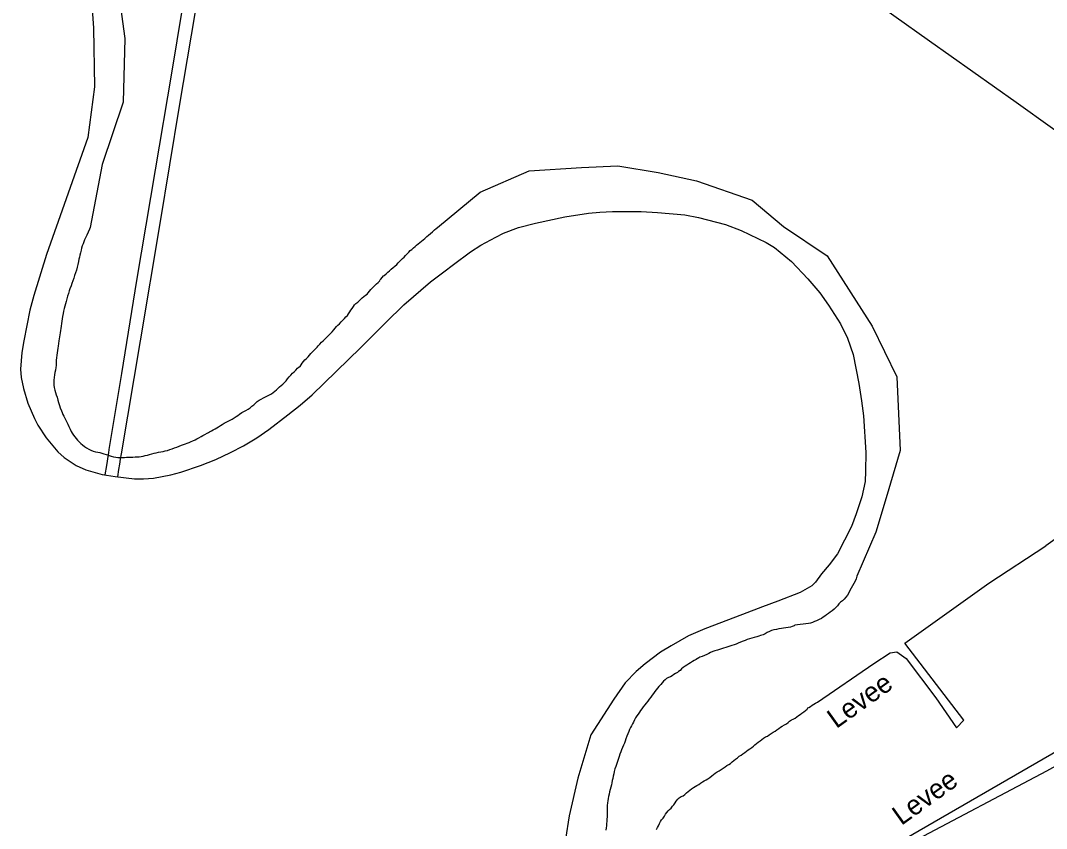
# Model space of a CAD drawing. Extents: x 2290055 to 2389491, y 66597 to 237875.
# Drawn here: x 2293627 to 2301445, y 205423 to 211575 of the extents above; entities that cross this region are included whole.
import ezdxf

# ---------------------------------------------------------------- set-up
doc = ezdxf.new("R2010")
doc.units = 0
for name, color, linetype in [('Exist Boundary Political CountyLine', 7, 'Continuous'), ('Exist Hydrographic Point Label', 7, 'Continuous'), ('Exist Hydrographic Pond Under 1500 Sq Ft', 7, 'Continuous'), ('Exist Hydrographic River Shore', 7, 'Continuous'), ('Exist Utilities Electrical Transmission Line', 7, 'Continuous')]:
    doc.layers.add(name, color=color, linetype=linetype)

msp = doc.modelspace()

# ---------------------------------------------------------------- linework, layer by layer
at = {"layer": 'Exist Boundary Political CountyLine'}
for points in [[(2294159.7, 211846.6), (2294184.2, 211516.4), (2294190.3, 211070.1), (2294141.4, 210685), (2293824.7, 209794.8), (2293728.2, 209481.7), (2293697.7, 209369.4), (2293652.4, 209136.9), (2293637.4, 209046.8), (2293627.3, 208920.3), (2293632.3, 208858), (2293649.3, 208774.3), (2293683.7, 208663.1), (2293732.8, 208546.1), (2293759.8, 208494.2), (2293822.9, 208399), (2293911.4, 208291.1), (2293958.8, 208248.6), (2294052.5, 208187), (2294125.9, 208154.6), (2294248.2, 208119.8), (2294347.6, 208102.7), (2294494.7, 208086.8), (2294564.6, 208085.7), (2294639.7, 208091.6), (2294773.9, 208115.4), (2294849.9, 208136.9), (2294997.5, 208186.6), (2295114.7, 208233.9), (2295226.1, 208285.1), (2295327.3, 208338.1), (2295426.8, 208397.6), (2295518.9, 208462.2), (2295664.8, 208572.3), (2295757, 208647.5), (2295849.1, 208726.3), (2296216.7, 209082.6), (2296410.5, 209276.8), (2296549, 209410.4), (2296751, 209584.6), (2296852, 209661.8), (2296927.5, 209716.8), (2297056.3, 209814.2), (2297134.3, 209863.7), (2297248.9, 209926.4), (2297308.6, 209955.1), (2297422, 209998.4), (2297550.2, 210032.3), (2297775.1, 210080.3), (2297954.8, 210108.4), (2298042.7, 210115.5), (2298138.6, 210120.6), (2298357.5, 210120.8), (2298480.6, 210114.6), (2298688.9, 210094.9), (2298793.1, 210076.1), (2298999.6, 210021.1), (2299118.3, 209976), (2299309.2, 209884.1), (2299372.9, 209846.5), (2299501, 209740.4), (2299626.6, 209607.8), (2299717.7, 209500.9), (2299784.8, 209407.8), (2299874.4, 209266.7), (2299929.1, 209156.6), (2299971.9, 209032.1), (2300015.8, 208812.5), (2300036.4, 208680.5), (2300050.5, 208564.9), (2300067.9, 208287.2), (2300066.5, 208145.1), (2300062.4, 208065.2), (2300037.3, 207947.9), (2299993.4, 207818.4), (2299958.4, 207723.9), (2299852.9, 207514.6), (2299787.9, 207431.9), (2299730.8, 207361.2), (2299685.4, 207298.7), (2299657.8, 207270.5), (2299567.7, 207221.3), (2299397.1, 207155.4), (2299281.6, 207110.1), (2299128.3, 207052.5), (2298841.7, 206943.1), (2298718.3, 206890.7), (2298585.3, 206813.7), (2298503.7, 206765.1), (2298386.7, 206677.8), (2298318.2, 206619.6), (2298234.5, 206532), (2298147.9, 206407.2), (2297972.4, 206136.3), (2297874.7, 205806.2), (2297807.5, 205518.9)], [(2297807.5, 205518.9), (2297752.5, 205164.3)]]:
    msp.add_lwpolyline(points, dxfattribs=at)
at = {"layer": 'Exist Hydrographic Pond Under 1500 Sq Ft'}
for points in [[(2302155.9, 208088.8), (2301438.9, 207576.2)], [(2299036.5, 205919), (2299049.5, 205930.2), (2299063.7, 205942), (2299076, 205951.6), (2299089.5, 205962.2), (2299104.2, 205973.2), (2299117.2, 205982.4), (2299131.7, 205992.6), (2299146, 206002.6), (2299158.7, 206012.4), (2299171.2, 206021.4), (2299185.2, 206030.8), (2299199.2, 206040.6), (2299211.5, 206050.4), (2299223.5, 206061.2), (2299235.5, 206071.2), (2299248.5, 206081.6), (2299262.2, 206090.8), (2299275, 206100.8), (2299288, 206111), (2299304.5, 206120), (2299318.5, 206127.2), (2299332.5, 206136.2), (2299347.2, 206146.4), (2299362.5, 206155.6), (2299377.7, 206165), (2299390.7, 206174.6), (2299404.5, 206185.6), (2299418, 206195), (2299431.7, 206203), (2299447.7, 206211.6), (2299462.7, 206221.2), (2299475.2, 206230.6), (2299487.2, 206240.2), (2299501, 206249.6), (2299515.5, 206256.6), (2299529.5, 206263.6), (2299542.5, 206273), (2299555.7, 206283.6), (2299568.5, 206292.4), (2299580.7, 206302), (2299595, 206312.4), (2299607.5, 206322.6), (2299620.2, 206332.8), (2299627.2, 206341.2), (2299632.7, 206344.4), (2299646.5, 206353.4), (2299659.2, 206362), (2299672.2, 206369.2), (2299685.5, 206378.8), (2299699.5, 206386), (2300128.3, 206679.5), (2300254.8, 206760.9), (2300304.5, 206767.6), (2300374.5, 206717.9), (2300600.4, 206417.3), (2300759.6, 206189), (2300816.1, 206247.8), (2300364.4, 206835.5), (2301004.7, 207292.1), (2301438.9, 207576.2)], [(2299997.5, 205070.8), (2300193.4, 205177), (2300418.3, 205320.4), (2301446.7, 205861.3), (2302287.4, 206326.6), (2302597.4, 206332.6), (2302606.3, 206332.6), (2302561.6, 206446), (2302317.2, 206469.8), (2300197.9, 205244.5), (2299971.5, 205121.2), (2299953.7, 205114.2), (2299938.2, 205104.6), (2299919.5, 205095.6), (2299905, 205087), (2299899, 205083.4)], [(2298472.5, 205416.8), (2298480.2, 205430), (2298488.5, 205444.2), (2298495.5, 205460), (2298502.7, 205475.6), (2298512.5, 205488.6), (2298524.5, 205502), (2298533.2, 205517.2), (2298542, 205531.6), (2298551.5, 205544.6), (2298561.7, 205557.4), (2298573.5, 205567.4), (2298584.5, 205579), (2298594.5, 205592.2), (2298604.2, 205604.4), (2298615.2, 205619), (2298623.7, 205631.6), (2298635.5, 205646.4), (2298646.5, 205657.2), (2298661.2, 205666.2), (2298675.5, 205673.2), (2298688.5, 205683.2), (2298701.5, 205694), (2298714.2, 205704.8), (2298727, 205715), (2298739.5, 205724.2), (2298755.5, 205734.8), (2298768.5, 205742.6), (2298781.7, 205750.2), (2298795, 205758.4), (2298808.5, 205767.8), (2298822.5, 205777.6), (2298836.5, 205786.4), (2298851, 205794), (2298865.2, 205802.4), (2298880, 205812.2), (2298893.7, 205823.2), (2298907.2, 205835.2), (2298920.7, 205844.8), (2298935.5, 205853.6), (2298951, 205862.4), (2298966.7, 205872.6), (2298980.2, 205882), (2298995.2, 205892.6), (2299009.7, 205902.6), (2299023.7, 205910.4), (2299036.5, 205919)]]:
    msp.add_lwpolyline(points, dxfattribs=at)
at = {"layer": 'Exist Hydrographic River Shore'}
for points in [[(2294356.4, 211924.3), (2294422.8, 211438.9), (2294409.5, 210953.4), (2294250.2, 210480.4), (2294158.2, 210000), (2294153.2, 209986.8), (2294143.5, 209963.8), (2294133.5, 209941.6), (2294123.5, 209921.8), (2294116, 209906.4), (2294109.5, 209890.4), (2294103.7, 209876.2), (2294098, 209859.4), (2294092.5, 209841.8), (2294088.2, 209826.2), (2294083.5, 209807.8), (2294079.2, 209789.6), (2294076, 209774.6), (2294072.7, 209757.4), (2294069.5, 209740.8), (2294064.7, 209718), (2294059.5, 209696.2), (2294053.2, 209675.2), (2294046.5, 209654.2), (2294039.7, 209633.4), (2294033.2, 209613.2), (2294026.5, 209593.6), (2294026.2, 209592.4), (2294019.5, 209574), (2294012.5, 209554.2), (2294004, 209532.2), (2293998.7, 209518), (2293992.2, 209497.8), (2293985.7, 209475.8), (2293980.5, 209456.2), (2293974.5, 209435.6), (2293969.7, 209418), (2293964.5, 209399.4), (2293960.2, 209382.6), (2293955.7, 209363.6), (2293952.2, 209344.6), (2293948.2, 209320.8), (2293945.7, 209303.8), (2293943.2, 209285.6), (2293940.7, 209267.4), (2293938.2, 209248.8), (2293935.5, 209230.8), (2293932.7, 209214), (2293930, 209198), (2293927, 209182.4), (2293924, 209167), (2293921.5, 209151.8), (2293919, 209136.6), (2293916.7, 209116.2), (2293914.5, 209096), (2293912.5, 209079.6), (2293909.7, 209063.4), (2293906.7, 209044.6), (2293904.2, 209026.2), (2293901.7, 209007.6), (2293900, 208989.2), (2293899, 208970.4), (2293897.7, 208949.8), (2293895.7, 208933.4), (2293892.7, 208913.8), (2293889.5, 208896), (2293886, 208876.4), (2293883.5, 208858.2), (2293881.5, 208837.4), (2293881, 208818.6), (2293882, 208798), (2293884.2, 208780.2), (2293889, 208760.8), (2293894.2, 208743.6), (2293900, 208725.4), (2293905.5, 208707.4), (2293912, 208685.8), (2293917.7, 208666), (2293924.2, 208644.8), (2293930.5, 208625.4), (2293938.5, 208603.8), (2293944.5, 208589.8), (2293950.7, 208575.6), (2293957.7, 208561.6), (2293967.7, 208541.8), (2293977.7, 208522), (2293987.5, 208502.6), (2293996.2, 208483.4), (2294004.5, 208464.8), (2294012.7, 208447.2), (2294020.5, 208433), (2294030.2, 208419.2), (2294040.5, 208406.6), (2294051.2, 208394), (2294062.7, 208381), (2294075.2, 208367.4), (2294087, 208355.2)], [(2296709, 209916.4), (2296722.2, 209930.2), (2296736.5, 209942), (2296750.5, 209953), (2296765.5, 209967.4), (2296780.7, 209980.6), (2296795.5, 209992.6), (2296804.5, 210000), (2297130.8, 210268.8), (2297502.4, 210430.7), (2297900.7, 210455.5), (2298179.4, 210468), (2298484.7, 210418.2), (2298776.8, 210356), (2299201.6, 210206.6), (2299440.5, 210007.4), (2299772.4, 209783.4), (2300117.5, 209248.2), (2300303.3, 208862.3), (2300329.9, 208302.2), (2300223.7, 207941.2), (2300144, 207679.8), (2300000, 207345.7), (2299999.7, 207345.2), (2299994.7, 207324.6), (2299987, 207307), (2299977.7, 207288.2), (2299967.5, 207271.6), (2299957, 207253.8), (2299946.5, 207235.6), (2299938, 207217.8), (2299927.5, 207199.4), (2299916.5, 207184.8), (2299903.7, 207169.4), (2299890, 207158), (2299876.2, 207147.4), (2299863.7, 207133.2), (2299851.2, 207118.2), (2299838.7, 207105.6), (2299826.5, 207092.2), (2299811.2, 207081.2), (2299796.5, 207071.6), (2299783, 207061.2), (2299769.5, 207050.6), (2299755.5, 207041.2), (2299743.2, 207031.4), (2299729.5, 207022), (2299711.5, 207013.4), (2299693.5, 207005.2), (2299678, 206998.4), (2299662, 206992.2), (2299647, 206987.2), (2299630.7, 206984.6), (2299528.5, 206970.2), (2299521.2, 206967), (2299507.2, 206961.2), (2299493.2, 206955), (2299475.7, 206952.8), (2299458.5, 206951.8), (2299441.7, 206949.2), (2299424.5, 206946), (2299406.2, 206942.8), (2299387, 206939), (2299368, 206935.2), (2299350.2, 206930), (2299333.5, 206923.6), (2299317.7, 206915), (2299302, 206905.4), (2299285, 206897.6), (2299266.7, 206892), (2299251.7, 206887.8), (2299237, 206883.8), (2299217, 206878), (2299199.2, 206872.4), (2299181.5, 206867), (2299164.7, 206861.8), (2299149, 206855.8), (2299132.5, 206848.6), (2299113.7, 206841.4), (2299094.7, 206834), (2299079, 206827.8), (2299064.5, 206822.6), (2299047.7, 206817.2), (2299032.7, 206812), (2299016.7, 206806), (2299001.7, 206800.8), (2298984.5, 206795.8), (2298969, 206791.4), (2298952.5, 206786.2), (2298937.5, 206781.8), (2298918.5, 206775.8), (2298903, 206769.8), (2298885.5, 206762.6), (2298871.2, 206755.8), (2298855.5, 206748.6), (2298839, 206741.2), (2298821.7, 206733.8), (2298804.5, 206726.6), (2298788.5, 206718.6), (2298785, 206716.6)], [(2295600.5, 208785), (2295612.7, 208795.6), (2295625.5, 208806.4), (2295638, 208818.2), (2295651, 208832.8), (2295662.2, 208847.2), (2295674.5, 208862.8), (2295686.5, 208876), (2295700.5, 208889.6), (2295712.5, 208901.2), (2295725, 208913.4), (2295738.2, 208927.2), (2295749.5, 208937.8), (2295757.5, 208940.2), (2295764.5, 208953.6), (2295773.2, 208966), (2295783.7, 208978.2), (2295793.7, 208990.8), (2295805.7, 209002), (2295818, 209014.4), (2295829, 209026.8), (2295839.5, 209039.4), (2295849.7, 209050.8), (2295861.7, 209062.2), (2295872.5, 209072.6), (2295884.5, 209084.6), (2295887, 209087.6), (2295896.5, 209098), (2295909.2, 209112.2), (2295921.5, 209125.2), (2295932.7, 209136.2), (2295945.2, 209148.4), (2295956.2, 209160.2), (2295968, 209171.4), (2295979.5, 209181.2), (2295991.7, 209194.4), (2296002.5, 209206.2), (2296013.5, 209219.4), (2296023.7, 209232.8), (2296034.5, 209245), (2296045.7, 209255), (2296058.5, 209267), (2296071.5, 209280.4), (2296082.7, 209293), (2296095, 209307), (2296107, 209318.2), (2296118.2, 209330.4), (2296127.2, 209343), (2296136.5, 209356.2), (2296143.7, 209369.6), (2296153.5, 209383.2), (2296163.5, 209397.4), (2296172, 209410), (2296183.5, 209419.8), (2296196.5, 209429.8), (2296207.2, 209441), (2296218, 209451.6), (2296231.5, 209463.4), (2296242.7, 209473.8), (2296256.5, 209483.8), (2296268.7, 209493), (2296277.5, 209501), (2296286.2, 209515), (2296296.2, 209526.8), (2296307.2, 209538.6), (2296318.5, 209549.6), (2296329.5, 209560), (2296340.5, 209570.6), (2296352.2, 209580.4), (2296363.7, 209590.4), (2296365, 209593.4), (2296363.5, 209595.6), (2296373.5, 209606.8), (2296393.7, 209630.4), (2296398.5, 209633.8), (2296414, 209647.2), (2296426.5, 209658.2), (2296439.5, 209670), (2296451.5, 209682.6), (2296467.5, 209695), (2296480.2, 209705.2), (2296494.7, 209718.2), (2296505.2, 209730.4), (2296516.2, 209741), (2296527.5, 209752.8), (2296538, 209763.4), (2296549.5, 209774.2), (2296560.7, 209787.2), (2296572.7, 209799.6), (2296585, 209811.6), (2296597, 209823.2), (2296609.5, 209832.8), (2296622.2, 209843.6), (2296633.2, 209853.8), (2296645, 209864.2), (2296656.7, 209874.2), (2296669, 209884.2), (2296682, 209895), (2296695.5, 209905.6), (2296709, 209916.4)], [(2294087, 208355.2), (2294098.5, 208344), (2294114.5, 208331), (2294130.5, 208320.8), (2294147.2, 208312), (2294164, 208303.8), (2294182, 208296.2), (2294199.7, 208291.4), (2294215.5, 208289), (2294231.5, 208285.4), (2294246, 208281.2), (2294261.5, 208276.8), (2294279.2, 208271.4), (2294294, 208268.6), (2294303, 208262.2), (2294318.5, 208257.8), (2294335.5, 208254), (2294352.7, 208249.8), (2294369, 208248), (2294384.5, 208248.2), (2294403.2, 208248.8), (2294419, 208249.4), (2294434, 208249.8), (2294450.5, 208250.4), (2294468.2, 208251), (2294484.2, 208251.4), (2294500.7, 208252), (2294516, 208252.4), (2294531, 208254), (2294546, 208255.6), (2294562.5, 208259.4), (2294577.2, 208262.4), (2294594.5, 208265.4), (2294611, 208270.2), (2294628.2, 208276.2), (2294645.5, 208280.8), (2294661.5, 208284.4), (2294677.5, 208287.8), (2294696.5, 208290.6), (2294713.5, 208293.6), (2294730.5, 208298), (2294746.5, 208302.6), (2294764.5, 208309), (2294782.5, 208315.2), (2294800.7, 208321.4), (2294818.5, 208327.8), (2294836.5, 208334.4), (2294854.7, 208341), (2294869, 208346.2), (2294883.2, 208351.8), (2294897.7, 208357.6), (2294912.2, 208363.2), (2294926.7, 208369), (2294940.7, 208374.6), (2294958, 208382.4), (2294971.5, 208389.2), (2294987, 208398.2), (2295003.2, 208407.4), (2295016.7, 208415), (2295032.5, 208423.4), (2295049.5, 208433), (2295060.7, 208439.4), (2295067.5, 208443.4), (2295081.5, 208450.4), (2295095.5, 208457.6), (2295110.5, 208465.8), (2295123.7, 208473.6), (2295136.5, 208482), (2295150.5, 208491.8), (2295164.2, 208500.2), (2295178.5, 208508.4), (2295194.5, 208517), (2295209, 208524.6), (2295225.5, 208532.6), (2295239.5, 208539.8), (2295256, 208550.2), (2295269.7, 208559.6), (2295282.7, 208569), (2295296.5, 208578.8), (2295313, 208589.6), (2295328.7, 208598.2), (2295344.5, 208606.2), (2295361, 208615.4), (2295376.2, 208626), (2295390.5, 208638), (2295404.5, 208650.4), (2295417.5, 208662.6), (2295431, 208674.2), (2295446.2, 208684.6), (2295462.2, 208693.4), (2295478.5, 208701.4), (2295493.7, 208709.2), (2295508.5, 208717), (2295524.5, 208725.2), (2295539.5, 208734), (2295552.7, 208742.8), (2295565.2, 208752.8), (2295576.7, 208763), (2295588.5, 208773.8), (2295600.5, 208785)], [(2298785, 206716.6), (2298774.2, 206710.6), (2298761, 206703), (2298746.5, 206694), (2298733.2, 206685.2), (2298720, 206676.4), (2298704.7, 206666.6), (2298690.5, 206658), (2298677.5, 206649.4), (2298663.7, 206639), (2298653.5, 206627), (2298641.5, 206618), (2298632.5, 206611.8), (2298618.5, 206603.8), (2298605.2, 206595.4), (2298592.5, 206586.6), (2298580.2, 206577.8), (2298565.7, 206571.8), (2298550.2, 206565), (2298538, 206555.8), (2298527.2, 206545)], [(2298527.2, 206545), (2298516.5, 206532.4), (2298505.5, 206520.2), (2298492, 206505.2), (2298481.2, 206491.8), (2298471.2, 206479.4), (2298460.2, 206465.6), (2298450, 206452.4), (2298439, 206437.6), (2298429, 206423.6), (2298417.5, 206408), (2298407, 206393.4), (2298395, 206378.2), (2298384.2, 206364.4), (2298372.5, 206349.2), (2298362.7, 206335.6), (2298352.2, 206321), (2298343, 206308), (2298332.7, 206293.8), (2298323.5, 206280.2), (2298313.7, 206264.6), (2298305.7, 206250), (2298297.7, 206233.4), (2298290.7, 206219.4), (2298283, 206204.8), (2298275.5, 206191.8), (2298267.5, 206176.4), (2298261.5, 206162), (2298253.7, 206142.8), (2298246.5, 206125.2), (2298240.5, 206106), (2298235, 206089.2), (2298229, 206073.8), (2298221.2, 206056.6), (2298213.7, 206040.6), (2298206.5, 206022.8), (2298201, 206007.6), (2298194, 205988), (2298188.2, 205972), (2298182.7, 205957), (2298177.5, 205940.8), (2298172.5, 205926.2), (2298167.5, 205910.4), (2298162.7, 205895.8), (2298156.7, 205876.4), (2298151.2, 205857.8), (2298147, 205839.2), (2298143.5, 205821.2), (2298139.7, 205804.4), (2298136.5, 205788), (2298133, 205771.4), (2298129.5, 205754.8), (2298125, 205738), (2298120.2, 205720.2), (2298115.7, 205701.4), (2298111.7, 205683.4), (2298108, 205666.4), (2298104.5, 205650.4), (2298101.2, 205634), (2298099.5, 205617.4), (2298098.5, 205599.4), (2298098.2, 205579), (2298098.5, 205562.2), (2298098.5, 205547.2), (2298098.2, 205531.2), (2298096.7, 205512.6), (2298095, 205494.4), (2298094.2, 205477.6), (2298093.5, 205462.2), (2298092.5, 205444.4), (2298089.7, 205428), (2298087.5, 205411.4)]]:
    msp.add_lwpolyline(points, dxfattribs=at)
at = {"layer": 'Exist Utilities Electrical Transmission Line'}
for p, q in [((2294283.9, 208188.3), (2294297.5, 208270.4)), ((2294389.6, 208236.6), (2294396.3, 208275.9)), ((2294272, 208115.7), (2294283.9, 208188.3)), ((2294367.6, 208100.5), (2294376.3, 208155.6))]:
    msp.add_line(p, q, dxfattribs=at)
for points in [[(2297521.2, 213577.2), (2297739.6, 213423.6), (2298439.1, 212929.8), (2299376.9, 212262.8), (2300010.2, 211808.1), (2300554.6, 211420.6), (2301214, 210954.2), (2301768.4, 210556.7), (2302026.3, 210375.9)], [(2294396.3, 208275.9), (2294542, 209137.2), (2294691.5, 210028.7), (2294839.1, 210922.5), (2294990.5, 211825.8), (2295080.7, 212347.2), (2295136.1, 212680)], [(2294303.7, 208308.6), (2294399.1, 208887.5), (2294514.5, 209596.6), (2294656.9, 210438.4), (2294780.1, 211173.6), (2294862.5, 211666.6), (2294972.9, 212315.8), (2295028.2, 212631.6)], [(2294297.5, 208270.4), (2294299.7, 208284.3), (2294303.7, 208308.6)], [(2294376.3, 208155.6), (2294383, 208197.4), (2294389.6, 208236.6)]]:
    msp.add_lwpolyline(points, dxfattribs=at)

# ---------------------------------------------------------------- texts
at = {"layer": 'Exist Hydrographic Point Label'}
for p in [(2299843.2, 206179.7), (2300338.9, 205442.2)]:
    msp.add_text('Levee', height=150, rotation=35.67641, dxfattribs=at).set_placement(p)

doc.saveas('drawing.dxf')
